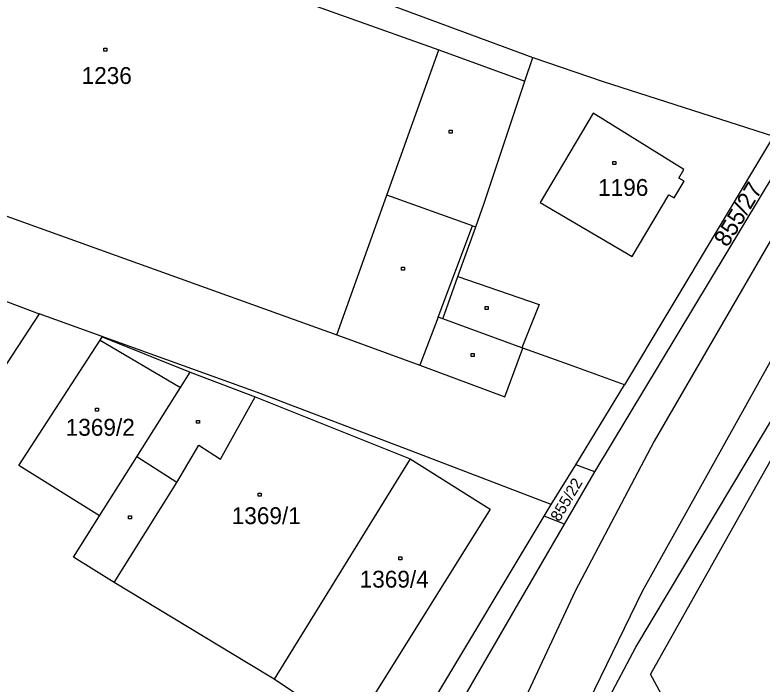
# Model space of a CAD drawing. Extents: x -711879 to -711361, y -1048782 to -1048177.
# Drawn here: x -711646.6 to -711571.3, y -1048371.7 to -1048304.3 of the extents above; entities that cross this region are included whole.
import ezdxf

# ---------------------------------------------------------------- set-up
doc = ezdxf.new("R2010")
doc.units = 0
for name, color, linetype in [('Vrstva 1', 7, 'Continuous'), ('Vrstva 14', 7, 'Continuous'), ('Vrstva 15', 7, 'Continuous'), ('Vrstva 2', 7, 'Continuous'), ('Vrstva 25', 7, 'Continuous'), ('Vrstva 46', 7, 'Continuous')]:
    doc.layers.add(name, color=color, linetype=linetype)

msp = doc.modelspace()

# ---------------------------------------------------------------- linework, layer by layer
at = {"layer": 'Vrstva 1'}
for p, q in [((-711642.81, -1048290.69), (-711594.43, -1048308.63)), ((-711558.97, -1048307.13), (-711582.21, -1048347.23)), ((-711595.22, -1048310.99), (-711594.43, -1048308.63)), ((-711594.43, -1048308.63), (-711587.33, -1048311.04)), ((-711599.36, -1048323.37), (-711595.22, -1048310.99)), ((-711587.33, -1048311.04), (-711570.19, -1048316.54)), ((-711555.05, -1048311.45), (-711583.43, -1048362.34)), ((-711671.04, -1048316.08), (-711614.15, -1048336.53)), ((-711570.19, -1048316.54), (-711580.92, -1048334.45)), ((-711584.04, -1048367.95), (-711554.12, -1048317.79)), ((-711588.19, -1048350.31), (-711569.92, -1048320.04)), ((-711600.17, -1048325.65), (-711599.36, -1048323.37)), ((-711601.96, -1048330.65), (-711600.17, -1048325.65)), ((-711665.35, -1048326.54), (-711644.11, -1048334.41)), ((-711603.49, -1048334.93), (-711601.96, -1048330.65)), ((-711644.11, -1048334.41), (-711647.9, -1048340.23)), ((-711622.15, -1048342.33), (-711644.11, -1048334.41)), ((-711595.54, -1048337.82), (-711603.49, -1048334.93)), ((-711580.92, -1048334.45), (-711585.18, -1048341.57)), ((-711614.15, -1048336.53), (-711605.79, -1048339.59)), ((-711646.17, -1048349.66), (-711637.98, -1048337.07)), ((-711637.98, -1048337.07), (-711637.76, -1048336.73)), ((-711637.76, -1048336.73), (-711628.9, -1048340.27)), ((-711597.24, -1048342.78), (-711595.41, -1048337.87)), ((-711595.41, -1048337.87), (-711595.54, -1048337.82)), ((-711590.74, -1048339.56), (-711595.41, -1048337.87)), ((-711605.79, -1048339.59), (-711597.24, -1048342.78)), ((-711585.18, -1048341.57), (-711590.74, -1048339.56)), ((-711628.9, -1048340.27), (-711622.37, -1048342.78)), ((-711590.1, -1048349.6), (-711585.18, -1048341.57)), ((-711606.6, -1048348.24), (-711622.15, -1048342.33)), ((-711625.86, -1048349.05), (-711622.37, -1048342.78)), ((-711622.37, -1048342.78), (-711606.78, -1048348.99)), ((-711568.18, -1048345.01), (-711582.56, -1048370.66)), ((-711630.25, -1048351.38), (-711628.04, -1048347.63)), ((-711628.04, -1048347.63), (-711625.86, -1048349.05)), ((-711582.21, -1048347.23), (-711590.17, -1048362.3)), ((-711592.56, -1048353.61), (-711606.6, -1048348.24)), ((-711606.78, -1048348.99), (-711620.44, -1048371.18)), ((-711606.78, -1048348.99), (-711598.7, -1048354.08)), ((-711638.03, -1048354.75), (-711646.17, -1048349.66)), ((-711592.56, -1048353.61), (-711590.1, -1048349.6)), ((-711588.19, -1048350.31), (-711590.1, -1048349.6)), ((-711591.24, -1048355.59), (-711588.19, -1048350.31)), ((-711636.57, -1048361.43), (-711630.25, -1048351.38)), ((-711593.27, -1048354.78), (-711592.56, -1048353.61)), ((-711598.7, -1048354.08), (-711612.66, -1048376.35)), ((-711640.66, -1048358.89), (-711638.03, -1048354.75)), ((-711607.76, -1048378.85), (-711593.27, -1048354.78)), ((-711591.24, -1048355.59), (-711593.27, -1048354.78)), ((-711595.83, -1048363.49), (-711591.24, -1048355.59)), ((-711636.57, -1048361.43), (-711640.66, -1048358.89)), ((-711623.08, -1048369.59), (-711636.57, -1048361.43)), ((-711590.17, -1048362.3), (-711596.67, -1048376.28)), ((-711583.43, -1048362.34), (-711589.37, -1048374.59)), ((-711617.37, -1048400.54), (-711595.83, -1048363.49)), ((-711587.04, -1048373.59), (-711584.04, -1048367.95)), ((-711620.44, -1048371.18), (-711623.08, -1048369.59)), ((-711613.07, -1048376.1), (-711620.44, -1048371.18)), ((-711581.05, -1048373.49), (-711582.56, -1048370.66))]:
    msp.add_line(p, q, dxfattribs=at)
at = {"layer": 'Vrstva 2'}
for p, q in [((-711660.67, -1048287.56), (-711603.88, -1048307.87)), ((-711609.11, -1048322.46), (-711603.88, -1048307.87)), ((-711603.88, -1048307.87), (-711595.22, -1048310.99)), ((-711588.33, -1048314.23), (-711593.68, -1048323.2)), ((-711579.21, -1048319.9), (-711588.33, -1048314.23)), ((-711579.72, -1048320.76), (-711579.21, -1048319.9)), ((-711579.2, -1048321.07), (-711579.72, -1048320.76)), ((-711580.2, -1048322.76), (-711579.2, -1048321.07)), ((-711614.15, -1048336.53), (-711609.11, -1048322.46)), ((-711600.5, -1048325.55), (-711609.11, -1048322.46)), ((-711584.43, -1048328.65), (-711580.73, -1048322.45)), ((-711580.73, -1048322.45), (-711580.2, -1048322.76)), ((-711593.68, -1048323.2), (-711584.43, -1048328.65)), ((-711603.96, -1048334.76), (-711600.5, -1048325.55)), ((-711600.5, -1048325.55), (-711600.17, -1048325.65)), ((-711601.96, -1048330.65), (-711593.78, -1048333.48)), ((-711593.78, -1048333.48), (-711595.54, -1048337.82)), ((-711603.96, -1048334.76), (-711605.79, -1048339.59)), ((-711603.49, -1048334.93), (-711603.96, -1048334.76)), ((-711637.98, -1048337.07), (-711629.88, -1048341.82)), ((-711629.88, -1048341.82), (-711628.9, -1048340.27)), ((-711634.27, -1048348.79), (-711629.88, -1048341.82)), ((-711638.03, -1048354.75), (-711634.27, -1048348.79)), ((-711630.25, -1048351.38), (-711634.27, -1048348.79))]:
    msp.add_line(p, q, dxfattribs=at)
at = {"layer": 'Vrstva 25'}
for p, q in [((-711637.61, -1048307.7), (-711637.31, -1048307.7)), ((-711637.61, -1048308), (-711637.61, -1048307.7)), ((-711637.31, -1048308), (-711637.61, -1048308)), ((-711637.31, -1048307.7), (-711637.31, -1048308)), ((-711602.84, -1048315.93), (-711602.54, -1048315.93)), ((-711602.84, -1048316.23), (-711602.84, -1048315.93)), ((-711602.54, -1048316.23), (-711602.84, -1048316.23)), ((-711602.54, -1048315.93), (-711602.54, -1048316.23)), ((-711586.38, -1048319.08), (-711586.08, -1048319.08)), ((-711586.38, -1048319.38), (-711586.38, -1048319.08)), ((-711586.08, -1048319.08), (-711586.08, -1048319.38)), ((-711586.08, -1048319.38), (-711586.38, -1048319.38)), ((-711607.65, -1048329.72), (-711607.35, -1048329.72)), ((-711607.65, -1048330.02), (-711607.65, -1048329.72)), ((-711607.35, -1048329.72), (-711607.35, -1048330.02)), ((-711607.35, -1048330.02), (-711607.65, -1048330.02)), ((-711599.22, -1048333.67), (-711598.92, -1048333.67)), ((-711599.22, -1048333.97), (-711599.22, -1048333.67)), ((-711598.92, -1048333.97), (-711599.22, -1048333.97)), ((-711598.92, -1048333.67), (-711598.92, -1048333.97)), ((-711600.63, -1048338.42), (-711600.33, -1048338.42)), ((-711600.63, -1048338.72), (-711600.63, -1048338.42)), ((-711600.33, -1048338.72), (-711600.63, -1048338.72)), ((-711600.33, -1048338.42), (-711600.33, -1048338.72)), ((-711638.45, -1048343.9), (-711638.15, -1048343.9)), ((-711638.45, -1048344.2), (-711638.45, -1048343.9)), ((-711638.15, -1048343.9), (-711638.15, -1048344.2)), ((-711638.15, -1048344.2), (-711638.45, -1048344.2)), ((-711628.28, -1048345.13), (-711627.98, -1048345.13)), ((-711628.28, -1048345.43), (-711628.28, -1048345.13)), ((-711627.98, -1048345.43), (-711628.28, -1048345.43)), ((-711627.98, -1048345.13), (-711627.98, -1048345.43)), ((-711622.07, -1048352.45), (-711621.77, -1048352.45)), ((-711622.07, -1048352.75), (-711622.07, -1048352.45)), ((-711621.77, -1048352.75), (-711622.07, -1048352.75)), ((-711621.77, -1048352.45), (-711621.77, -1048352.75)), ((-711635.13, -1048354.73), (-711634.83, -1048354.73)), ((-711635.13, -1048355.03), (-711635.13, -1048354.73)), ((-711634.83, -1048355.03), (-711635.13, -1048355.03)), ((-711634.83, -1048354.73), (-711634.83, -1048355.03)), ((-711607.9, -1048358.85), (-711607.6, -1048358.85)), ((-711607.9, -1048359.15), (-711607.9, -1048358.85)), ((-711607.6, -1048359.15), (-711607.9, -1048359.15)), ((-711607.6, -1048358.85), (-711607.6, -1048359.15))]:
    msp.add_line(p, q, dxfattribs=at)
at = {"layer": 'Vrstva 46'}
for p, q in [((-711603.88, -1048307.87), (-711603.88, -1048307.87)), ((-711588.33, -1048314.23), (-711588.33, -1048314.23)), ((-711579.21, -1048319.9), (-711579.21, -1048319.9)), ((-711579.72, -1048320.76), (-711579.72, -1048320.76)), ((-711579.2, -1048321.07), (-711579.2, -1048321.07)), ((-711580.73, -1048322.45), (-711580.73, -1048322.45)), ((-711580.2, -1048322.76), (-711580.2, -1048322.76)), ((-711593.68, -1048323.2), (-711593.68, -1048323.2)), ((-711584.43, -1048328.65), (-711584.43, -1048328.65)), ((-711644.11, -1048334.41), (-711644.11, -1048334.41)), ((-711603.96, -1048334.76), (-711603.96, -1048334.76)), ((-711580.92, -1048334.45), (-711580.92, -1048334.45)), ((-711614.15, -1048336.53), (-711614.15, -1048336.53)), ((-711637.76, -1048336.73), (-711637.76, -1048336.73)), ((-711595.41, -1048337.87), (-711595.41, -1048337.87)), ((-711605.79, -1048339.59), (-711605.79, -1048339.59)), ((-711590.74, -1048339.56), (-711590.74, -1048339.56)), ((-711628.9, -1048340.27), (-711628.9, -1048340.27)), ((-711622.37, -1048342.78), (-711622.37, -1048342.78)), ((-711606.78, -1048348.99), (-711606.78, -1048348.99)), ((-711646.17, -1048349.66), (-711646.17, -1048349.66)), ((-711630.25, -1048351.38), (-711630.25, -1048351.38)), ((-711592.56, -1048353.61), (-711592.56, -1048353.61)), ((-711598.7, -1048354.08), (-711598.7, -1048354.08)), ((-711638.03, -1048354.75), (-711638.03, -1048354.75)), ((-711640.66, -1048358.89), (-711640.66, -1048358.89)), ((-711636.57, -1048361.43), (-711636.57, -1048361.43)), ((-711623.08, -1048369.59), (-711623.08, -1048369.59)), ((-711620.44, -1048371.18), (-711620.44, -1048371.18))]:
    msp.add_line(p, q, dxfattribs=at)

# ---------------------------------------------------------------- texts
at = {"layer": 'Vrstva 14'}
for s, height, rotation, p in [('855/27', 1.7, 58.78908, (-711574.838, -1048327.794)), ('855/22', 1.14, 59.33547, (-711591.747, -1048355.388))]:
    msp.add_text(s, height=height, rotation=rotation, dxfattribs=at).set_placement(p)
at = {"layer": 'Vrstva 15'}
for s, p in [('1236', (-711639.84, -1048311.29)), ('1196', (-711587.85, -1048322.55)), ('1369/2', (-711641.44, -1048346.68)), ('1369/1', (-711624.73, -1048355.57)), ('1369/4', (-711611.85, -1048361.96))]:
    msp.add_text(s, height=1.7, dxfattribs=at).set_placement(p)

doc.saveas('drawing.dxf')
